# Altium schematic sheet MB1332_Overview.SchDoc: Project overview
size A4; Date: Not used; ApprovedBy: Not used; CheckedBy: Not used; Author: Not used; CompanyName: STMicroelectronics; DrawnBy: Not used; Engineer: Not used; Organization: Not used; Address1: Not used; Address2: Not used; Address3: Not used; Address4: Not used; DocumentNumber: 1; Revision: Not used; SheetNumber: 1; SheetTotal: 17
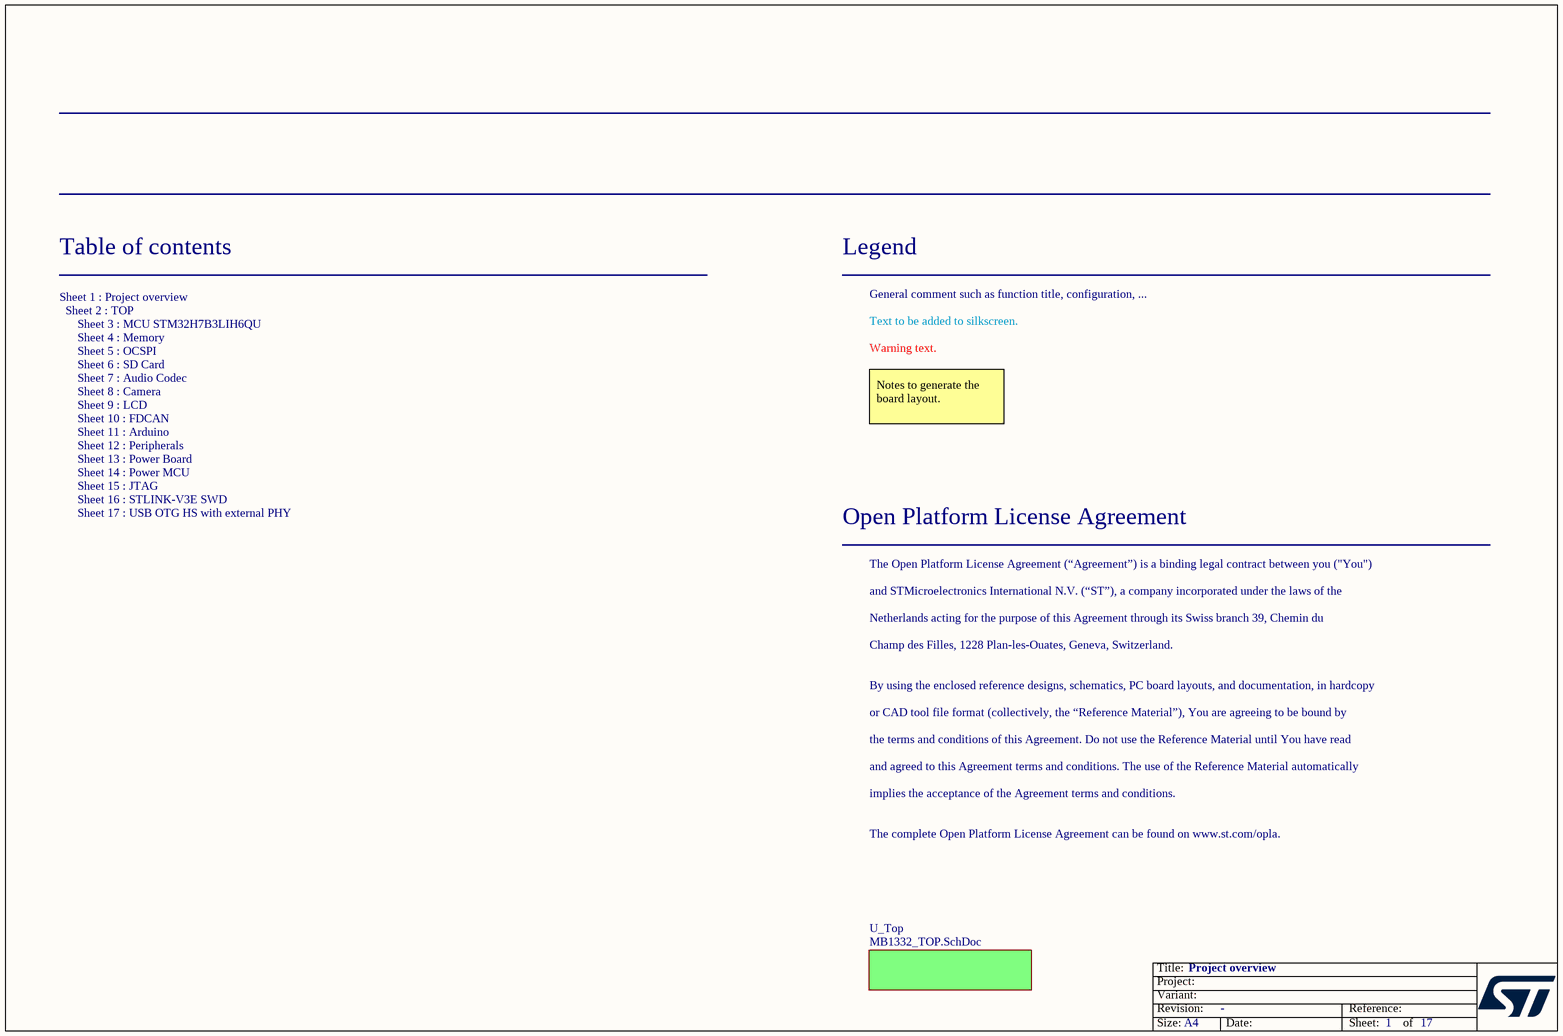
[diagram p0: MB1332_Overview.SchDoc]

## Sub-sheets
U_Top = MB1332_TOP.SchDoc: no entries

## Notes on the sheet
- Table of contents
- Legend
- General comment such as function title, configuration, ...
- Text to be added to silkscreen.
- Warning text.
- Notes to generate the board layout.
- Sheet 1 : Project overview
  Sheet 2 : TOP
  Sheet 3 : MCU STM32H7B3LIH6QU
  Sheet 4 : Memory
  Sheet 5 : OCSPI
  Sheet 6 : SD Card
  Sheet 7 : Audio Codec
  Sheet 8 : Camera
  Sheet 9 : LCD
  Sheet 10 : FDCAN
  Sheet 11 : Arduino
  Sheet 12 : Peripherals
  Sheet 13 : Power Board
  Sheet 14 : Power MCU
  Sheet 15 : JTAG
  Sheet 16 : STLINK-V3E SWD
  Sheet 17 : USB OTG HS with external PHY
- Open Platform License Agreement
- The Open Platform License Agreement (“Agreement”) is a binding legal contract between you ("You")
- and STMicroelectronics International N.V. (“ST”), a company incorporated under the laws of the
- Netherlands acting for the purpose of this Agreement through its Swiss branch 39, Chemin du
- Champ des Filles, 1228 Plan-les-Ouates, Geneva, Switzerland.
- By using the enclosed reference designs, schematics, PC board layouts, and documentation, in hardcopy
- or CAD tool file format (collectively, the “Reference Material”), You are agreeing to be bound by
- the terms and conditions of this Agreement. Do not use the Reference Material until You have read
- and agreed to this Agreement terms and conditions. The use of the Reference Material automatically
- implies the acceptance of the Agreement terms and conditions.
- The complete Open Platform License Agreement can be found on www.st.com/opla.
